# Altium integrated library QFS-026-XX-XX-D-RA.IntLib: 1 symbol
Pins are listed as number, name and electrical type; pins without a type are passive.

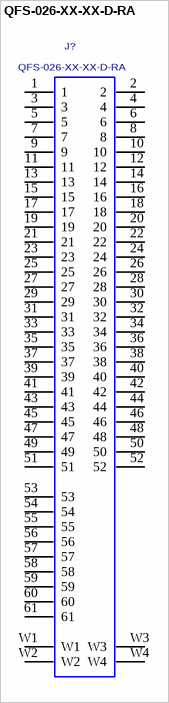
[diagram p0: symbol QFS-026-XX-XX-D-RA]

## QFS-026-XX-XX-D-RA
designator J?
0.635MM DUAL ROW RIGHT ANGLE SOCKET ASSEMBLY.; MANUFACTURER: SAMTEC
footprint QFS-026-XX-XX-D-RA
pins: 1, 2, 3, 4, 5, 6, 7, 8, 9, 10, 11, 12, 13, 14, 15, 16, 17, 18, 19, 20, 21, 22, 23, 24, 25, 26, 27, 28, 29, 30, 31, 32, 33, 34, 35, 36, 37, 38, 39, 40, 41, 42, 43, 44, 45, 46, 47, 48, 49, 50, 51, 52, 53, 54, 55, 56, 57, 58, 59, 60, 61, W1, W2, W3, W4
